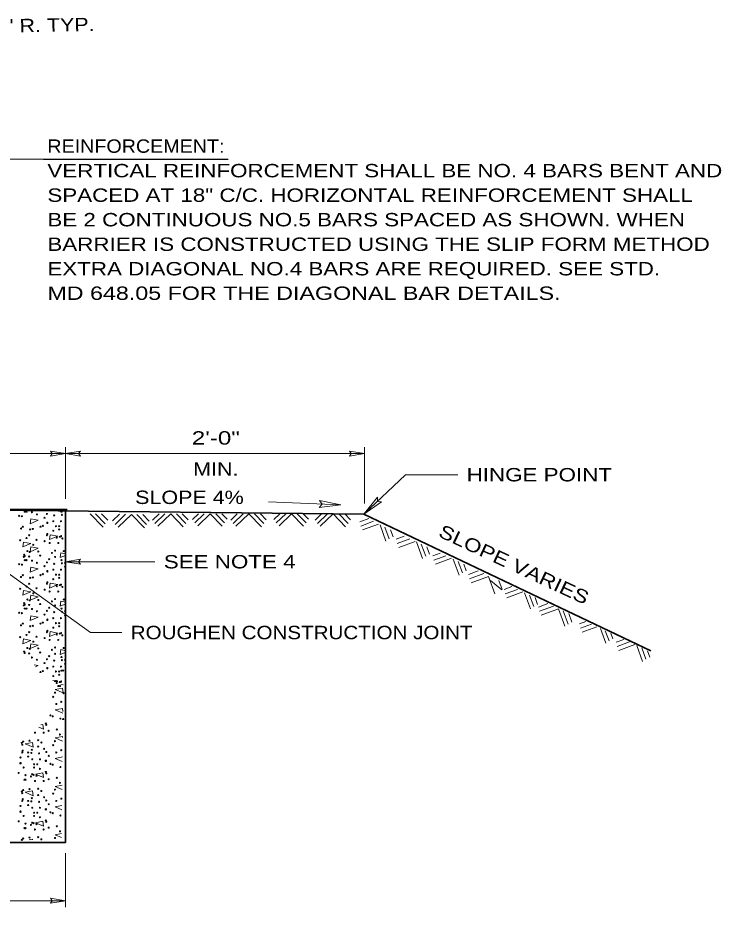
# Model space of a CAD drawing. Extents: x -16.43 to -9.36, y -8.57 to 1.26.
# Drawn here: x -12.904 to -9.749, y -3.289 to 0.702 of the extents above; entities that cross this region are included whole.
import ezdxf
from ezdxf.enums import TextEntityAlignment as Align

# ---------------------------------------------------------------- set-up
doc = ezdxf.new("R2010")
doc.units = 0
doc.header["$LTSCALE"] = 0.024
for name, color, linetype, lineweight in [('1', 7, 'Continuous', 35), ('10', 7, 'Continuous', 13), ('12', 7, 'Continuous', 53), ('6', 7, 'Continuous', 13)]:
    doc.layers.add(name, color=color, linetype=linetype, lineweight=lineweight)

msp = doc.modelspace()

# ---------------------------------------------------------------- linework, layer by layer
at = {"layer": '1'}
for p, q in [((-11.35133, -1.526), (-13.28633, -1.504)), ((-13.07283, -1.504), (-12.68283, -1.504)), ((-12.69033, -2.99817), (-12.69033, -1.504)), ((-11.35133, -1.526), (-10.06417, -2.13917)), ((-14.66667, -2.99817), (-12.69033, -2.99817))]:
    msp.add_line(p, q, dxfattribs=at)
at = {"layer": '10'}
for p, q in [((-13.08117, 0.06817), (-12.78867, 0.06817)), ((-12.69033, -1.456), (-12.69033, -1.2245)), ((-11.3495, -1.478), (-11.3495, -1.2245)), ((-12.7575, -1.24217), (-12.69033, -1.25333)), ((-12.7575, -1.24217), (-12.749, -1.25333)), ((-12.7575, -1.2645), (-12.69033, -1.25333)), ((-12.7575, -1.2645), (-12.749, -1.25333)), ((-12.623, -1.24217), (-12.69033, -1.25333)), ((-12.623, -1.2645), (-12.69033, -1.25333)), ((-12.623, -1.24217), (-12.6315, -1.25333)), ((-12.623, -1.2645), (-12.6315, -1.25333)), ((-11.41667, -1.24217), (-11.3495, -1.25333)), ((-11.41667, -1.24217), (-11.40833, -1.25333)), ((-11.41667, -1.2645), (-11.3495, -1.25333)), ((-11.41667, -1.2645), (-11.40833, -1.25333)), ((-11.16433, -1.34833), (-11.35133, -1.526)), ((-11.16433, -1.34833), (-10.931, -1.34833)), ((-11.77917, -1.46983), (-11.455, -1.484)), ((-11.55017, -1.46383), (-11.455, -1.484)), ((-11.55017, -1.46383), (-11.539, -1.48033)), ((-11.29133, -1.44983), (-11.35133, -1.526)), ((-11.27217, -1.47), (-11.35133, -1.526)), ((-11.29133, -1.44983), (-11.2905, -1.46817)), ((-11.27217, -1.47), (-11.2905, -1.46817)), ((-11.55167, -1.49583), (-11.539, -1.48033)), ((-11.55167, -1.49583), (-11.455, -1.484)), ((-12.623, -1.72767), (-12.69033, -1.73883)), ((-12.69033, -1.73883), (-12.289, -1.73883)), ((-12.623, -1.75), (-12.69033, -1.73883)), ((-12.623, -1.72767), (-12.6315, -1.73883)), ((-12.623, -1.75), (-12.6315, -1.73883)), ((-12.69017, -3.04617), (-12.69017, -3.289)), ((-12.69017, -3.26017), (-14.66583, -3.26017)), ((-12.75733, -3.249), (-12.69017, -3.26017)), ((-12.75733, -3.249), (-12.749, -3.26017)), ((-12.75733, -3.27133), (-12.69017, -3.26017)), ((-12.75733, -3.27133), (-12.749, -3.26017))]:
    msp.add_line(p, q, dxfattribs=at)
at = {"layer": '10', "lineweight": 25}
msp.add_line((-12.78867, 0.06817), (-11.96067, 0.06817), dxfattribs=at)
at = {"layer": '10'}
for points in [[(-13.28633, -1.25333), (-12.69033, -1.25333), (-11.3495, -1.25333)], [(-13.345, -1.5045), (-12.57717, -2.05633), (-12.43733, -2.05633)]]:
    msp.add_lwpolyline(points, dxfattribs=at)
at = {"layer": '6'}
for p, q in [((-12.579, -1.5235), (-12.5215, -1.58317)), ((-12.512, -1.5685), (-12.55567, -1.52317)), ((-12.52783, -1.52367), (-12.49967, -1.55283)), ((-12.47883, -1.55533), (-12.44767, -1.52517)), ((-12.42, -1.5255), (-12.467, -1.571)), ((-12.32633, -1.57167), (-12.37017, -1.5265)), ((-12.34233, -1.527), (-12.31417, -1.55617)), ((-12.299, -1.552), (-12.27, -1.524)), ((-12.244, -1.524), (-12.28867, -1.56717)), ((-12.15033, -1.567), (-12.192, -1.524)), ((-12.166, -1.524), (-12.14, -1.55083)), ((-12.12, -1.54967), (-12.09333, -1.524)), ((-12.06733, -1.524), (-12.10983, -1.565)), ((-11.976, -1.56467), (-12.01533, -1.524)), ((-11.98933, -1.524), (-11.9655, -1.5485)), ((-11.9485, -1.552), (-11.91967, -1.524)), ((-11.89367, -1.524), (-11.93833, -1.56717)), ((-11.8, -1.567), (-11.84167, -1.524)), ((-11.81567, -1.524), (-11.78967, -1.55083)), ((-11.75483, -1.54967), (-11.72817, -1.524)), ((-11.70217, -1.524), (-11.74467, -1.565)), ((-11.61083, -1.56467), (-11.65017, -1.524)), ((-11.62417, -1.524), (-11.60033, -1.5485)), ((-11.5705, -1.552), (-11.5415, -1.524)), ((-11.5155, -1.524), (-11.56017, -1.56717)), ((-11.42183, -1.567), (-11.4635, -1.524)), ((-11.4375, -1.524), (-11.4115, -1.55083)), ((-11.3705, -1.55933), (-11.32933, -1.54433)), ((-11.30817, -1.5575), (-11.366, -1.57867)), ((-11.3585, -1.59633), (-11.28567, -1.56983)), ((-11.279, -1.57283), (-11.2525, -1.646)), ((-11.23783, -1.63633), (-11.25717, -1.58333)), ((-11.23183, -1.595), (-11.22017, -1.62717)), ((-11.20733, -1.63733), (-11.17067, -1.62383)), ((-11.1455, -1.63567), (-11.20267, -1.6565)), ((-11.19517, -1.67433), (-11.121, -1.64733)), ((-11.11633, -1.6495), (-11.08933, -1.72383)), ((-11.0745, -1.71433), (-11.09433, -1.65983)), ((-11.06917, -1.67167), (-11.057, -1.70517)), ((-11.04267, -1.71217), (-11.009, -1.7)), ((-10.98383, -1.71183), (-11.03817, -1.7315)), ((-11.03067, -1.74933), (-10.95933, -1.72333)), ((-10.95067, -1.7275), (-10.92467, -1.79883)), ((-10.90983, -1.78933), (-10.92867, -1.73767)), ((-10.9035, -1.74967), (-10.89233, -1.78017)), ((-10.882, -1.79583), (-10.83867, -1.78)), ((-10.8135, -1.79183), (-10.8775, -1.81517)), ((-10.73367, -1.86417), (-10.78367, -1.82233)), ((-10.7465, -1.8235), (-10.73183, -1.86383)), ((-10.72283, -1.86317), (-10.6885, -1.85067)), ((-10.66333, -1.86267), (-10.71817, -1.8825)), ((-10.71067, -1.90017), (-10.63883, -1.87417)), ((-10.631, -1.87783), (-10.60467, -1.94983)), ((-10.59, -1.94033), (-10.609, -1.88817)), ((-10.58383, -1.9), (-10.5725, -1.93117)), ((-10.56867, -1.942), (-10.52683, -1.92683)), ((-10.50167, -1.93867), (-10.56417, -1.96133)), ((-10.436, -2.019), (-10.45783, -1.95917)), ((-10.4325, -1.97117), (-10.4185, -2.01)), ((-10.38483, -2.01733), (-10.3565, -2.007)), ((-10.33133, -2.01883), (-10.38017, -2.0365)), ((-10.37283, -2.05433), (-10.30683, -2.03033)), ((-10.29083, -2.03783), (-10.26683, -2.10383)), ((-10.252, -2.09433), (-10.269, -2.04817)), ((-10.24367, -2.06), (-10.2345, -2.08517)), ((-10.22, -2.09933), (-10.18617, -2.08717)), ((-10.161, -2.09883), (-10.2155, -2.11867)), ((-10.208, -2.1365), (-10.1365, -2.1105)), ((-10.128, -2.11433), (-10.102, -2.186)), ((-10.08717, -2.1765), (-10.10583, -2.1255)), ((-10.08017, -2.13867), (-10.06967, -2.16733)), ((-12.81233, -2.205), (-12.83033, -2.2015)), ((-12.824, -2.21), (-12.81233, -2.205)), ((-12.72483, -2.27633), (-12.746, -2.27217)), ((-12.70067, -2.3275), (-12.7365, -2.31217)), ((-12.733, -2.27967), (-12.72483, -2.27633)), ((-12.711, -2.29017), (-12.70733, -2.2895)), ((-12.70733, -2.29183), (-12.711, -2.29017)), ((-12.70383, -2.29017), (-12.70017, -2.2895)), ((-12.70017, -2.29183), (-12.70383, -2.29017)), ((-12.70167, -2.41867), (-12.7365, -2.40367)), ((-12.70383, -2.5075), (-12.7025, -2.50733)), ((-12.70267, -2.50817), (-12.70383, -2.5075)), ((-12.703, -2.54383), (-12.7365, -2.5295)), ((-12.7365, -2.621), (-12.70367, -2.61467)), ((-12.704, -2.635), (-12.7365, -2.621)), ((-12.7365, -2.74683), (-12.70517, -2.74067)), ((-12.70533, -2.76017), (-12.7365, -2.74683)), ((-12.7365, -2.8385), (-12.70617, -2.8325)), ((-12.70633, -2.85133), (-12.7365, -2.8385)), ((-12.7365, -2.96417), (-12.7075, -2.9585)), ((-12.70783, -2.9765), (-12.7365, -2.96417))]:
    msp.add_line(p, q, dxfattribs=at)
for points in [[(-12.81233, -1.553), (-12.8455, -1.5465), (-12.84833, -1.56833)], [(-12.72483, -1.62417), (-12.75783, -1.61767), (-12.76083, -1.63967)], [(-12.845, -1.65683), (-12.878, -1.65033), (-12.88083, -1.67217)], [(-12.81233, -1.67867), (-12.8455, -1.67217), (-12.84833, -1.694)], [(-12.81233, -1.77033), (-12.8455, -1.76383), (-12.84833, -1.78567)], [(-12.72483, -1.8415), (-12.75783, -1.835), (-12.76083, -1.857)], [(-12.845, -1.87417), (-12.878, -1.86767), (-12.88083, -1.8895)], [(-12.81233, -1.896), (-12.8455, -1.8895), (-12.84833, -1.9115)], [(-12.81233, -1.98767), (-12.8455, -1.98117), (-12.84833, -2.003)], [(-12.72483, -2.05883), (-12.75783, -2.05233), (-12.76083, -2.07433)], [(-12.845, -2.0915), (-12.878, -2.085), (-12.88083, -2.10683)], [(-12.81233, -2.11333), (-12.8455, -2.10683), (-12.84833, -2.12883)], [(-12.87083, -2.556), (-12.83767, -2.5495), (-12.83483, -2.57133)], [(-12.824, -2.69233), (-12.791, -2.68583), (-12.788, -2.70767)], [(-12.87083, -2.77333), (-12.83767, -2.76683), (-12.83483, -2.78867)], [(-12.824, -2.90967), (-12.791, -2.90317), (-12.788, -2.925)]]:
    msp.add_lwpolyline(points, close=True, dxfattribs=at)
for points in [[(-12.453, -1.58417), (-12.3935, -1.52683), (-12.33583, -1.58633)], [(-12.27583, -1.57983), (-12.218, -1.524), (-12.16183, -1.582)], [(-12.097, -1.57767), (-12.04133, -1.524), (-11.9875, -1.57967)], [(-11.9255, -1.57983), (-11.86767, -1.524), (-11.8115, -1.582)], [(-11.73183, -1.57767), (-11.67617, -1.524), (-11.62233, -1.57967)], [(-11.54733, -1.57983), (-11.4895, -1.524), (-11.4335, -1.582)], [(-12.69017, -1.70283), (-12.711, -1.69867), (-12.714, -1.7205), (-12.69017, -1.71033)], [(-10.87, -1.833), (-10.79233, -1.80467), (-10.764, -1.8825)], [(-12.68883, -1.92033), (-12.711, -1.916), (-12.714, -1.938), (-12.68883, -1.92717)], [(-10.55667, -1.97917), (-10.47917, -1.95083), (-10.45067, -2.02867)], [(-12.68767, -2.138), (-12.711, -2.13333), (-12.714, -2.15533), (-12.6875, -2.144)], [(-12.7365, -2.31217), (-12.70333, -2.30567), (-12.70067, -2.32683)], [(-12.7365, -2.40367), (-12.70333, -2.39717), (-12.7015, -2.4115)], [(-12.79967, -2.47017), (-12.791, -2.4685), (-12.788, -2.49033), (-12.80983, -2.481)], [(-12.7365, -2.5295), (-12.70333, -2.523), (-12.70283, -2.5275)], [(-12.85317, -2.98717), (-12.83767, -2.98417), (-12.83733, -2.98717)]]:
    msp.add_lwpolyline(points, dxfattribs=at)
for centre in [(-12.87284, -1.51437), (-12.86468, -1.51437), (-12.84027, -1.51641), (-12.70793, -1.51437), (-12.89728, -1.53269), (-12.88504, -1.53473), (-12.81787, -1.52657), (-12.78399, -1.54145), (-12.77306, -1.52453), (-12.74458, -1.55714), (-12.7405, -1.53065), (-12.70997, -1.55714), (-12.70589, -1.52861), (-12.88912, -1.5897), (-12.881, -1.58154), (-12.8484, -1.59378), (-12.83619, -1.59174), (-12.80159, -1.58154), (-12.79139, -1.5775), (-12.77106, -1.56322), (-12.77106, -1.56526), (-12.73238, -1.5795), (-12.71809, -1.5795), (-12.71809, -1.59378), (-12.86468, -1.63247), (-12.85248, -1.62023), (-12.77306, -1.62023), (-12.77106, -1.61415), (-12.74458, -1.59986), (-12.72902, -1.63103), (-12.71537, -1.62667), (-12.70973, -1.62423), (-12.70385, -1.63447), (-12.8932, -1.64263), (-12.83415, -1.66299), (-12.81991, -1.64059), (-12.78326, -1.64671), (-12.76086, -1.65483), (-12.72218, -1.65483), (-12.87692, -1.71748), (-12.87488, -1.70728), (-12.87284, -1.7134), (-12.86064, -1.691), (-12.85248, -1.71544), (-12.85044, -1.69508), (-12.81175, -1.69304), (-12.80363, -1.71136), (-12.7507, -1.69916), (-12.73642, -1.68896), (-12.73642, -1.71748), (-12.69773, -1.691), (-12.89728, -1.75005), (-12.88504, -1.75209), (-12.87284, -1.73172), (-12.86468, -1.73172), (-12.84027, -1.73376), (-12.81787, -1.74393), (-12.77306, -1.74189), (-12.7629, -1.72764), (-12.7405, -1.74801), (-12.70793, -1.73172), (-12.70589, -1.74597), (-12.69165, -1.74393), (-12.79139, -1.79485), (-12.78399, -1.75881), (-12.77106, -1.78057), (-12.77106, -1.78261), (-12.74458, -1.77449), (-12.73238, -1.79686), (-12.71809, -1.79686), (-12.70997, -1.77449), (-12.69165, -1.76225), (-12.88912, -1.80706), (-12.881, -1.7989), (-12.85248, -1.83758), (-12.8484, -1.81114), (-12.83619, -1.8091), (-12.80159, -1.7989), (-12.77306, -1.83758), (-12.77106, -1.8315), (-12.74458, -1.81722), (-12.71809, -1.81114), (-12.8932, -1.85999), (-12.86468, -1.84982), (-12.81991, -1.85794), (-12.78326, -1.86407), (-12.76086, -1.87219), (-12.72902, -1.84838), (-12.72218, -1.87219), (-12.71537, -1.84402), (-12.70973, -1.84158), (-12.70385, -1.85182), (-12.86064, -1.90835), (-12.85044, -1.91243), (-12.83415, -1.88035), (-12.81175, -1.91039), (-12.7507, -1.91651), (-12.73642, -1.90631), (-12.69773, -1.90835), (-12.87692, -1.93484), (-12.87488, -1.92464), (-12.87284, -1.93076), (-12.87284, -1.94908), (-12.86468, -1.94908), (-12.85248, -1.9328), (-12.84027, -1.95112), (-12.80363, -1.92872), (-12.7629, -1.945), (-12.73642, -1.93484), (-12.70793, -1.94908), (-12.89728, -1.9674), (-12.88504, -1.96944), (-12.81787, -1.96128), (-12.78399, -1.97616), (-12.77306, -1.95924), (-12.77106, -1.99793), (-12.74458, -1.99185), (-12.7405, -1.96536), (-12.70997, -1.99185), (-12.70589, -1.96332), (-12.69165, -1.96128), (-12.69165, -1.9796), (-12.88912, -2.02441), (-12.881, -2.01625), (-12.8484, -2.02849), (-12.83619, -2.02645), (-12.80159, -2.01625), (-12.79139, -2.01221), (-12.77106, -1.99997), (-12.74458, -2.03457), (-12.73238, -2.01421), (-12.71809, -2.01421), (-12.71809, -2.02849), (-12.8932, -2.07734), (-12.86468, -2.06718), (-12.85248, -2.05494), (-12.81991, -2.0753), (-12.77306, -2.05494), (-12.77106, -2.04886), (-12.72902, -2.06574), (-12.71537, -2.06138), (-12.70973, -2.05894), (-12.70385, -2.06918), (-12.83415, -2.0977), (-12.78326, -2.08142), (-12.76086, -2.08954), (-12.72218, -2.08954), (-12.87488, -2.14199), (-12.87284, -2.14811), (-12.86064, -2.12571), (-12.85248, -2.15015), (-12.85044, -2.12979), (-12.81175, -2.12775), (-12.80363, -2.14607), (-12.7507, -2.13387), (-12.73642, -2.12367), (-12.73642, -2.15219), (-12.69773, -2.12571), (-12.84027, -2.16847), (-12.81787, -2.17864), (-12.78399, -2.19352), (-12.77306, -2.1766), (-12.7629, -2.16235), (-12.7405, -2.18272), (-12.70793, -2.16643), (-12.70589, -2.18068), (-12.69165, -2.17864), (-12.69165, -2.19696), (-12.80159, -2.2336), (-12.79139, -2.22956), (-12.77106, -2.21528), (-12.77106, -2.21732), (-12.74458, -2.2092), (-12.73238, -2.23156), (-12.71809, -2.23156), (-12.70997, -2.2092), (-12.70751, -2.2272), (-12.70039, -2.2272), (-12.74458, -2.25193), (-12.73599, -2.27401), (-12.72887, -2.27401), (-12.71809, -2.24585), (-12.70973, -2.27629), (-12.72902, -2.28309), (-12.72175, -2.29641), (-12.71537, -2.27873), (-12.71463, -2.29641), (-12.74516, -2.34478), (-12.73704, -2.32646), (-12.69835, -2.3285), (-12.73091, -2.37735), (-12.70851, -2.36719), (-12.7574, -2.42828), (-12.7472, -2.43232), (-12.77772, -2.46492), (-12.77572, -2.471), (-12.71259, -2.44252), (-12.70039, -2.44456), (-12.82661, -2.50561), (-12.78792, -2.50561), (-12.76552, -2.49749), (-12.72887, -2.49137), (-12.71463, -2.51377), (-12.88566, -2.55198), (-12.87954, -2.54585), (-12.85105, -2.54177), (-12.81237, -2.53973), (-12.79809, -2.54994), (-12.73704, -2.54381), (-12.88362, -2.5601), (-12.88362, -2.5947), (-12.88158, -2.58658), (-12.85713, -2.5947), (-12.84085, -2.5825), (-12.81237, -2.56826), (-12.78588, -2.57842), (-12.77572, -2.59266), (-12.74516, -2.56214), (-12.73091, -2.5947), (-12.70851, -2.58454), (-12.89174, -2.61711), (-12.85713, -2.61303), (-12.84289, -2.59674), (-12.83881, -2.62527), (-12.80829, -2.59878), (-12.80421, -2.62527), (-12.77772, -2.63135), (-12.77772, -2.63339), (-12.7648, -2.60959), (-12.89174, -2.64155), (-12.89174, -2.64359), (-12.8775, -2.66191), (-12.83069, -2.64763), (-12.83069, -2.66191), (-12.81641, -2.64763), (-12.80421, -2.66799), (-12.7574, -2.64563), (-12.7472, -2.64967), (-12.71259, -2.65987), (-12.8999, -2.68632), (-12.86938, -2.69652), (-12.84493, -2.7026), (-12.83905, -2.69236), (-12.83341, -2.6948), (-12.81977, -2.69916), (-12.77772, -2.68228), (-12.77572, -2.68836), (-12.76552, -2.71484), (-12.72887, -2.70872), (-12.87342, -2.71688), (-12.86938, -2.71688), (-12.82661, -2.72296), (-12.78792, -2.72296), (-12.71463, -2.73112), (-12.88566, -2.76933), (-12.88362, -2.77745), (-12.87954, -2.76321), (-12.85105, -2.75913), (-12.81237, -2.75709), (-12.81237, -2.78561), (-12.79809, -2.76729), (-12.78588, -2.79577), (-12.74516, -2.77949), (-12.73704, -2.76117), (-12.89174, -2.83446), (-12.88362, -2.81206), (-12.88158, -2.80394), (-12.85713, -2.81206), (-12.85713, -2.83038), (-12.84289, -2.8141), (-12.84085, -2.79986), (-12.80829, -2.81614), (-12.77572, -2.81002), (-12.7648, -2.82694), (-12.73091, -2.81206), (-12.70851, -2.8019), (-12.89174, -2.8589), (-12.89174, -2.86095), (-12.83881, -2.84262), (-12.83069, -2.86499), (-12.81641, -2.86499), (-12.80421, -2.84262), (-12.77772, -2.8487), (-12.77772, -2.85074), (-12.7574, -2.86299), (-12.7472, -2.86703), (-12.8999, -2.90367), (-12.8775, -2.87927), (-12.86938, -2.91387), (-12.83905, -2.90971), (-12.83341, -2.91215), (-12.83069, -2.87927), (-12.80421, -2.88535), (-12.77772, -2.89963), (-12.77572, -2.90571), (-12.71259, -2.87723), (-12.87342, -2.93424), (-12.86938, -2.93424), (-12.84493, -2.91995), (-12.82661, -2.94032), (-12.81977, -2.91651), (-12.78792, -2.94032), (-12.76552, -2.9322), (-12.72887, -2.92608), (-12.71463, -2.94848), (-12.88566, -2.98669), (-12.87954, -2.98056), (-12.85105, -2.97648), (-12.81237, -2.97444), (-12.79809, -2.98465), (-12.73704, -2.97852)]:
    msp.add_circle(centre, 0.00252, dxfattribs=at)
msp.add_arc((-12.89098, -2.86003), 0.00553, 273.03799, 273.05914, dxfattribs=at)

# ---------------------------------------------------------------- texts
at = {"layer": '12', "width": 1.2}
msp.add_text('3/4" R. TYP.', height=0.06001, rotation=1, dxfattribs=at).set_placement((-13.0905, 0.63342))
at = {"layer": '12'}
for s, width, p in [('REINFORCEMENT:', 1.1, (-12.77108, 0.09608)), ('VERTICAL REINFORCEMENT SHALL BE NO. 4 BARS BENT AND', 1.25, (-12.77108, -0.01392)), ('SPACED AT 18" C/C. HORIZONTAL REINFORCEMENT SHALL', 1.25, (-12.77108, -0.12392)), ('BE 2 CONTINUOUS NO.5 BARS SPACED AS SHOWN. WHEN', 1.25, (-12.77108, -0.23392)), ('BARRIER IS CONSTRUCTED USING THE SLIP FORM METHOD', 1.25, (-12.77108, -0.344)), ('EXTRA DIAGONAL NO.4 BARS ARE REQUIRED. SEE STD.', 1.25, (-12.77108, -0.454)), ('MD 648.05 FOR THE DIAGONAL BAR DETAILS.', 1.3, (-12.77108, -0.56392)), ('HINGE POINT', 1.25, (-10.891, -1.37833)), ('SEE NOTE 4', 1.25, (-12.24892, -1.76883)), ('ROUGHEN CONSTRUCTION JOINT', 1.15, (-12.39725, -2.08642))]:
    msp.add_text(s, height=0.06001, dxfattribs=dict(at, width=width)).set_placement(p)
for s, width, p in [('2\'-0"', 1.35, (-12.01558, -1.21325)), ('MIN.', 1.2, (-12.01558, -1.35325))]:
    msp.add_text(s, height=0.06001, dxfattribs=dict(at, width=width)).set_placement(p, align=Align.CENTER)
at = {"layer": '12', "width": 1.2}
msp.add_text('SLOPE 4%', height=0.06001, dxfattribs=at).set_placement((-11.89042, -1.47975), align=Align.RIGHT)
at = {"layer": '12', "width": 1.25}
msp.add_text('SLOPE VARIES', height=0.06001, rotation=335, dxfattribs=at).set_placement((-10.69118, -1.77817), align=Align.CENTER)

doc.saveas('drawing.dxf')
